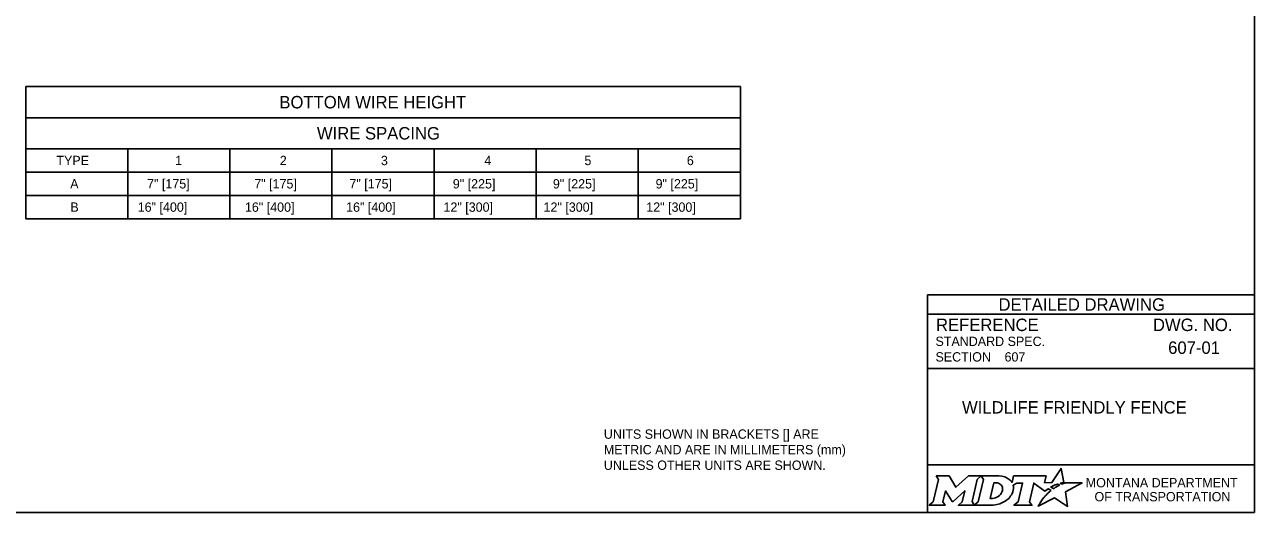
# Model space of a CAD drawing. Extents: x 49991.4 to 50021, y 49987.6 to 50011.4.
# Drawn here: x 50013.03 to 50020.94, y 49999.89 to 50003.02 of the extents above; entities that cross this region are included whole.
import ezdxf

# ---------------------------------------------------------------- set-up
doc = ezdxf.new("R2010")
doc.units = 0
for name, color, linetype in [('Default', 7, 'Continuous'), ('Level 1', 7, 'Continuous'), ('Level 2', 7, 'Continuous'), ('Level 4', 7, 'Continuous')]:
    doc.layers.add(name, color=color, linetype=linetype)

msp = doc.modelspace()

# ---------------------------------------------------------------- linework, layer by layer
at = {"layer": 'Default'}
for points in [[(50019.7003, 50000.0679), (50019.69, 50000.0735), (50019.7016, 50000.0763), (50019.7132, 50000.0783), (50019.6958, 50000.1684), (50019.6363, 50000.0771), (50019.589, 50000.0764), (50019.5993, 50000.1205), (50019.3901, 50000.1206), (50019.38, 50000.0781), (50019.3742, 50000.0864)], [(50018.8933, 50000.1206), (50018.9074, 50000.0972), (50018.8739, 49999.9539), (50018.8482, 49999.9314), (50018.9498, 49999.9314), (50018.9363, 49999.9542), (50018.9525, 50000.0243), (50018.9962, 49999.9553), (50019.0015, 49999.9553), (50019.0766, 50000.0248), (50019.0602, 49999.9537), (50019.0355, 49999.9317), (50019.1371, 49999.9317), (50019.1233, 49999.955), (50019.1565, 50000.0974)], [(50019.1565, 50000.0974), (50019.1818, 50000.1206), (50019.0994, 50000.1206), (50019.0198, 50000.0476), (50018.9753, 50000.1203), (50018.8933, 50000.1206)], [(50019.2954, 50000.1206), (50019.1818, 50000.1206), (50019.1965, 50000.0977), (50019.1626, 49999.9539), (50019.1371, 49999.9317), (50019.2477, 49999.9317)], [(50019.3194, 50000.0339), (50019.3182, 50000.0258), (50019.315, 50000.0165), (50019.3108, 50000.0083), (50019.3052, 50000.0008), (50019.2987, 49999.9939), (50019.2908, 49999.9876), (50019.2825, 49999.9829), (50019.2734, 49999.979), (50019.2643, 49999.9767), (50019.2551, 49999.9758), (50019.2392, 49999.9758), (50019.2628, 50000.0758), (50019.2788, 50000.0758), (50019.2864, 50000.0752), (50019.294, 50000.0733), (50019.3006, 50000.0703), (50019.3067, 50000.0661), (50019.3115, 50000.0611), (50019.3152, 50000.0551), (50019.3179, 50000.0489), (50019.3195, 50000.0415), (50019.3195, 50000.0385), (50019.3194, 50000.0339)], [(50019.3868, 50000.0615), (50019.4114, 50000.0746), (50019.4483, 50000.0746), (50019.4197, 49999.9541), (50019.3922, 49999.9314), (50019.5084, 49999.9314), (50019.4914, 49999.9543), (50019.5196, 50000.0745), (50019.5909, 50000.0228), (50019.612, 50000.0379), (50019.6317, 50000.027)], [(50019.5759, 49999.9711), (50019.5606, 49999.9467), (50019.5559, 49999.9392), (50019.5501, 49999.9306), (50019.5478, 49999.9263), (50019.6531, 49999.9794), (50019.737, 49999.9243), (50019.7239, 50000.017), (50019.8308, 50000.0754), (50019.7815, 50000.0762), (50019.7514, 50000.0766), (50019.7306, 50000.0769), (50019.7238, 50000.0754), (50019.7189, 50000.0742), (50019.7105, 50000.0719), (50019.7003, 50000.0679)], [(50019.6499, 50000.0403), (50019.6475, 50000.0386), (50019.6292, 50000.0482), (50019.6395, 50000.0539), (50019.6436, 50000.0561), (50019.6522, 50000.0601), (50019.6579, 50000.0627), (50019.6658, 50000.0657), (50019.6731, 50000.0684), (50019.6849, 50000.061), (50019.6809, 50000.0589), (50019.6763, 50000.0564), (50019.6721, 50000.0542), (50019.6671, 50000.0513), (50019.6652, 50000.0502), (50019.6625, 50000.0486), (50019.66, 50000.0472), (50019.6577, 50000.0456), (50019.6551, 50000.0438), (50019.6524, 50000.042), (50019.6499, 50000.0403)], [(50019.5898, 49999.9872), (50019.5898, 49999.9872)], [(50019.2934, 49999.939), (50019.3018, 49999.9416), (50019.3148, 49999.947), (50019.3352, 49999.958)]]:
    msp.add_lwpolyline(points, dxfattribs=at)
for centre, radius, start, end in [((50019.3185, 50000.0422), 0.0709, 339.53292, 15.85821), ((50019.2745, 50000.0595), 0.1183, 300.91025, 339.13831)]:
    msp.add_arc(centre, radius, start, end, dxfattribs=at)
for centre, major_axis, ratio, start_param, end_param in [((50019.2933, 50000.0732), (0.0834, -0.0037), 0.568097, 0.61298, 1.570796), ((50019.3489, 50000.0805), (0.0361, -0.0295), 0.469099, 1.225588, 1.570796), ((50019.5829, 49999.9791), (-0.00694, -0.00806), 0.008222, 0, 3.137361), ((50019.5996, 49999.9974), (-0.0098, -0.0102), 0.016458, 3.141593, 6.279097), ((50019.6206, 50000.0173), (-0.0112, -0.0097), 0.021651, 3.157348, 6.283185), ((50019.248, 50000.08), (0, 0.1484), 0.987302, 3.139398, 3.456847)]:
    msp.add_ellipse(centre, major_axis=major_axis, ratio=ratio, start_param=start_param, end_param=end_param, dxfattribs=at)
at = {"layer": 'Level 1'}
msp.add_lwpolyline([(50020.9378, 50008.1646), (50009.7374, 50008.1646), (50009.7374, 49999.8856), (50020.9378, 49999.8856)], close=True, dxfattribs=at)
msp.add_lwpolyline([(50020.9378, 50008.1646), (50009.7374, 50008.1646), (50009.7374, 49999.8856), (50020.9378, 49999.8856)], close=True, dxfattribs=at)
at = {"layer": 'Level 2'}
for p, q in [((50013.041, 50002.4244), (50017.6342, 50002.4244)), ((50017.6342, 50002.2244), (50013.041, 50002.2244)), ((50013.6971, 50002.2244), (50013.6971, 50001.7744)), ((50014.3533, 50002.2244), (50014.3533, 50001.7744)), ((50015.0095, 50002.2244), (50015.0095, 50001.7744)), ((50015.6657, 50002.2244), (50015.6657, 50001.7744)), ((50016.3218, 50002.2244), (50016.3218, 50001.7744)), ((50016.978, 50002.2244), (50016.978, 50001.7744)), ((50013.041, 50002.0744), (50017.6342, 50002.0744)), ((50013.041, 50001.9244), (50017.6342, 50001.9244))]:
    msp.add_line(p, q, dxfattribs=at)
msp.add_lwpolyline([(50013.041, 50002.6244), (50017.6342, 50002.6244), (50017.6342, 50001.7744), (50013.041, 50001.7744)], close=True, dxfattribs=at)
at = {"layer": 'Level 4'}
for p, q in [((50020.9378, 50001.2856), (50018.8378, 50001.2856)), ((50018.8378, 50001.2856), (50018.8378, 49999.8856)), ((50020.9378, 50001.1606), (50018.8378, 50001.1606)), ((50020.5739, 50000.9455), (50020.5739, 50000.9455)), ((50019.3321, 50000.8861), (50019.3321, 50000.8861)), ((50020.9378, 50000.8106), (50018.8378, 50000.8106)), ((50019.8878, 50000.5615), (50019.8878, 50000.5615)), ((50020.9378, 50000.1925), (50018.8378, 50000.1925))]:
    msp.add_line(p, q, dxfattribs=at)

# ---------------------------------------------------------------- texts
at = {"layer": 'Default'}
for s, p in [('MONTANA DEPARTMENT', (50019.854, 50000.0468)), ('OF TRANSPORTATION', (50019.9102, 49999.9568))]:
    msp.add_text(s, height=0.06, rotation=360, dxfattribs=at).set_placement(p)
at = {"layer": 'Level 2'}
for s, height, p in [('BOTTOM WIRE HEIGHT', 0.08, (50014.6715, 50002.4844)), ('WIRE SPACING', 0.08, (50014.9127, 50002.2844)), ('TYPE', 0.06, (50013.2384, 50002.1194)), ('1', 0.06, (50014.0015, 50002.1194)), ('2', 0.06, (50014.674, 50002.1194)), ('3', 0.06, (50015.3241, 50002.1194)), ('4', 0.06, (50015.9888, 50002.1194)), ('5', 0.06, (50016.6319, 50002.1194)), ('6', 0.06, (50017.2903, 50002.1194)), ('A', 0.06, (50013.3272, 50001.9694)), ('7" [175]', 0.06, (50013.821, 50001.9694)), ('7" [175]', 0.06, (50014.5101, 50001.9694)), ('7" [175]', 0.06, (50015.1214, 50001.9694)), ('9" [225]', 0.06, (50015.7861, 50001.9694)), ('9" [225]', 0.06, (50016.4292, 50001.9694)), ('9" [225]', 0.06, (50017.0893, 50001.9694)), ('B', 0.06, (50013.3282, 50001.8194)), ('16" [400]', 0.06, (50013.761, 50001.8194)), ('16" [400]', 0.06, (50014.4501, 50001.8194)), ('16" [400]', 0.06, (50015.1002, 50001.8194)), ('12" [300]', 0.06, (50015.7261, 50001.8194)), ('12" [300]', 0.06, (50016.3692, 50001.8194)), ('12" [300]', 0.06, (50017.0293, 50001.8194)), ('607', 0.06, (50019.3321, 50000.8561)), ('607-01', 0.08, (50020.3834, 50000.9055)), ('WILDLIFE FRIENDLY FENCE', 0.08, (50019.0586, 50000.5215)), ('UNITS SHOWN IN BRACKETS [] ARE ', 0.06, (50016.7567, 50000.3594)), ('METRIC AND ARE IN MILLIMETERS (mm) ', 0.06, (50016.7567, 50000.2594)), ('UNLESS OTHER UNITS ARE SHOWN.', 0.06, (50016.7567, 50000.1594))]:
    msp.add_text(s, height=height, dxfattribs=at).set_placement(p)
at = {"layer": 'Level 4'}
for s, height, p in [('DETAILED DRAWING', 0.08, (50019.2931, 50001.1831)), ('REFERENCE', 0.08, (50018.8914, 50001.0522)), ('DWG. NO.', 0.08, (50020.2856, 50001.0522)), ('STANDARD SPEC.', 0.06, (50018.8881, 50000.9562)), ('SECTION', 0.06, (50018.8881, 50000.8562))]:
    msp.add_text(s, height=height, dxfattribs=at).set_placement(p)

doc.saveas('drawing.dxf')
